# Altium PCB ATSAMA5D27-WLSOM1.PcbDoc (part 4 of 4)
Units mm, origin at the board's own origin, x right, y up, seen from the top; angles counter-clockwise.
Board outline 40.8 x 40.8 mm, 6 copper layers (L1 - Top, L2 - GND, L3 - Signal, L4 - Signal, L5 - PWR, L6 - Bottom), stack 1.144 mm thick; 196 components, 221 nets, 1038 pads, 713 vias.
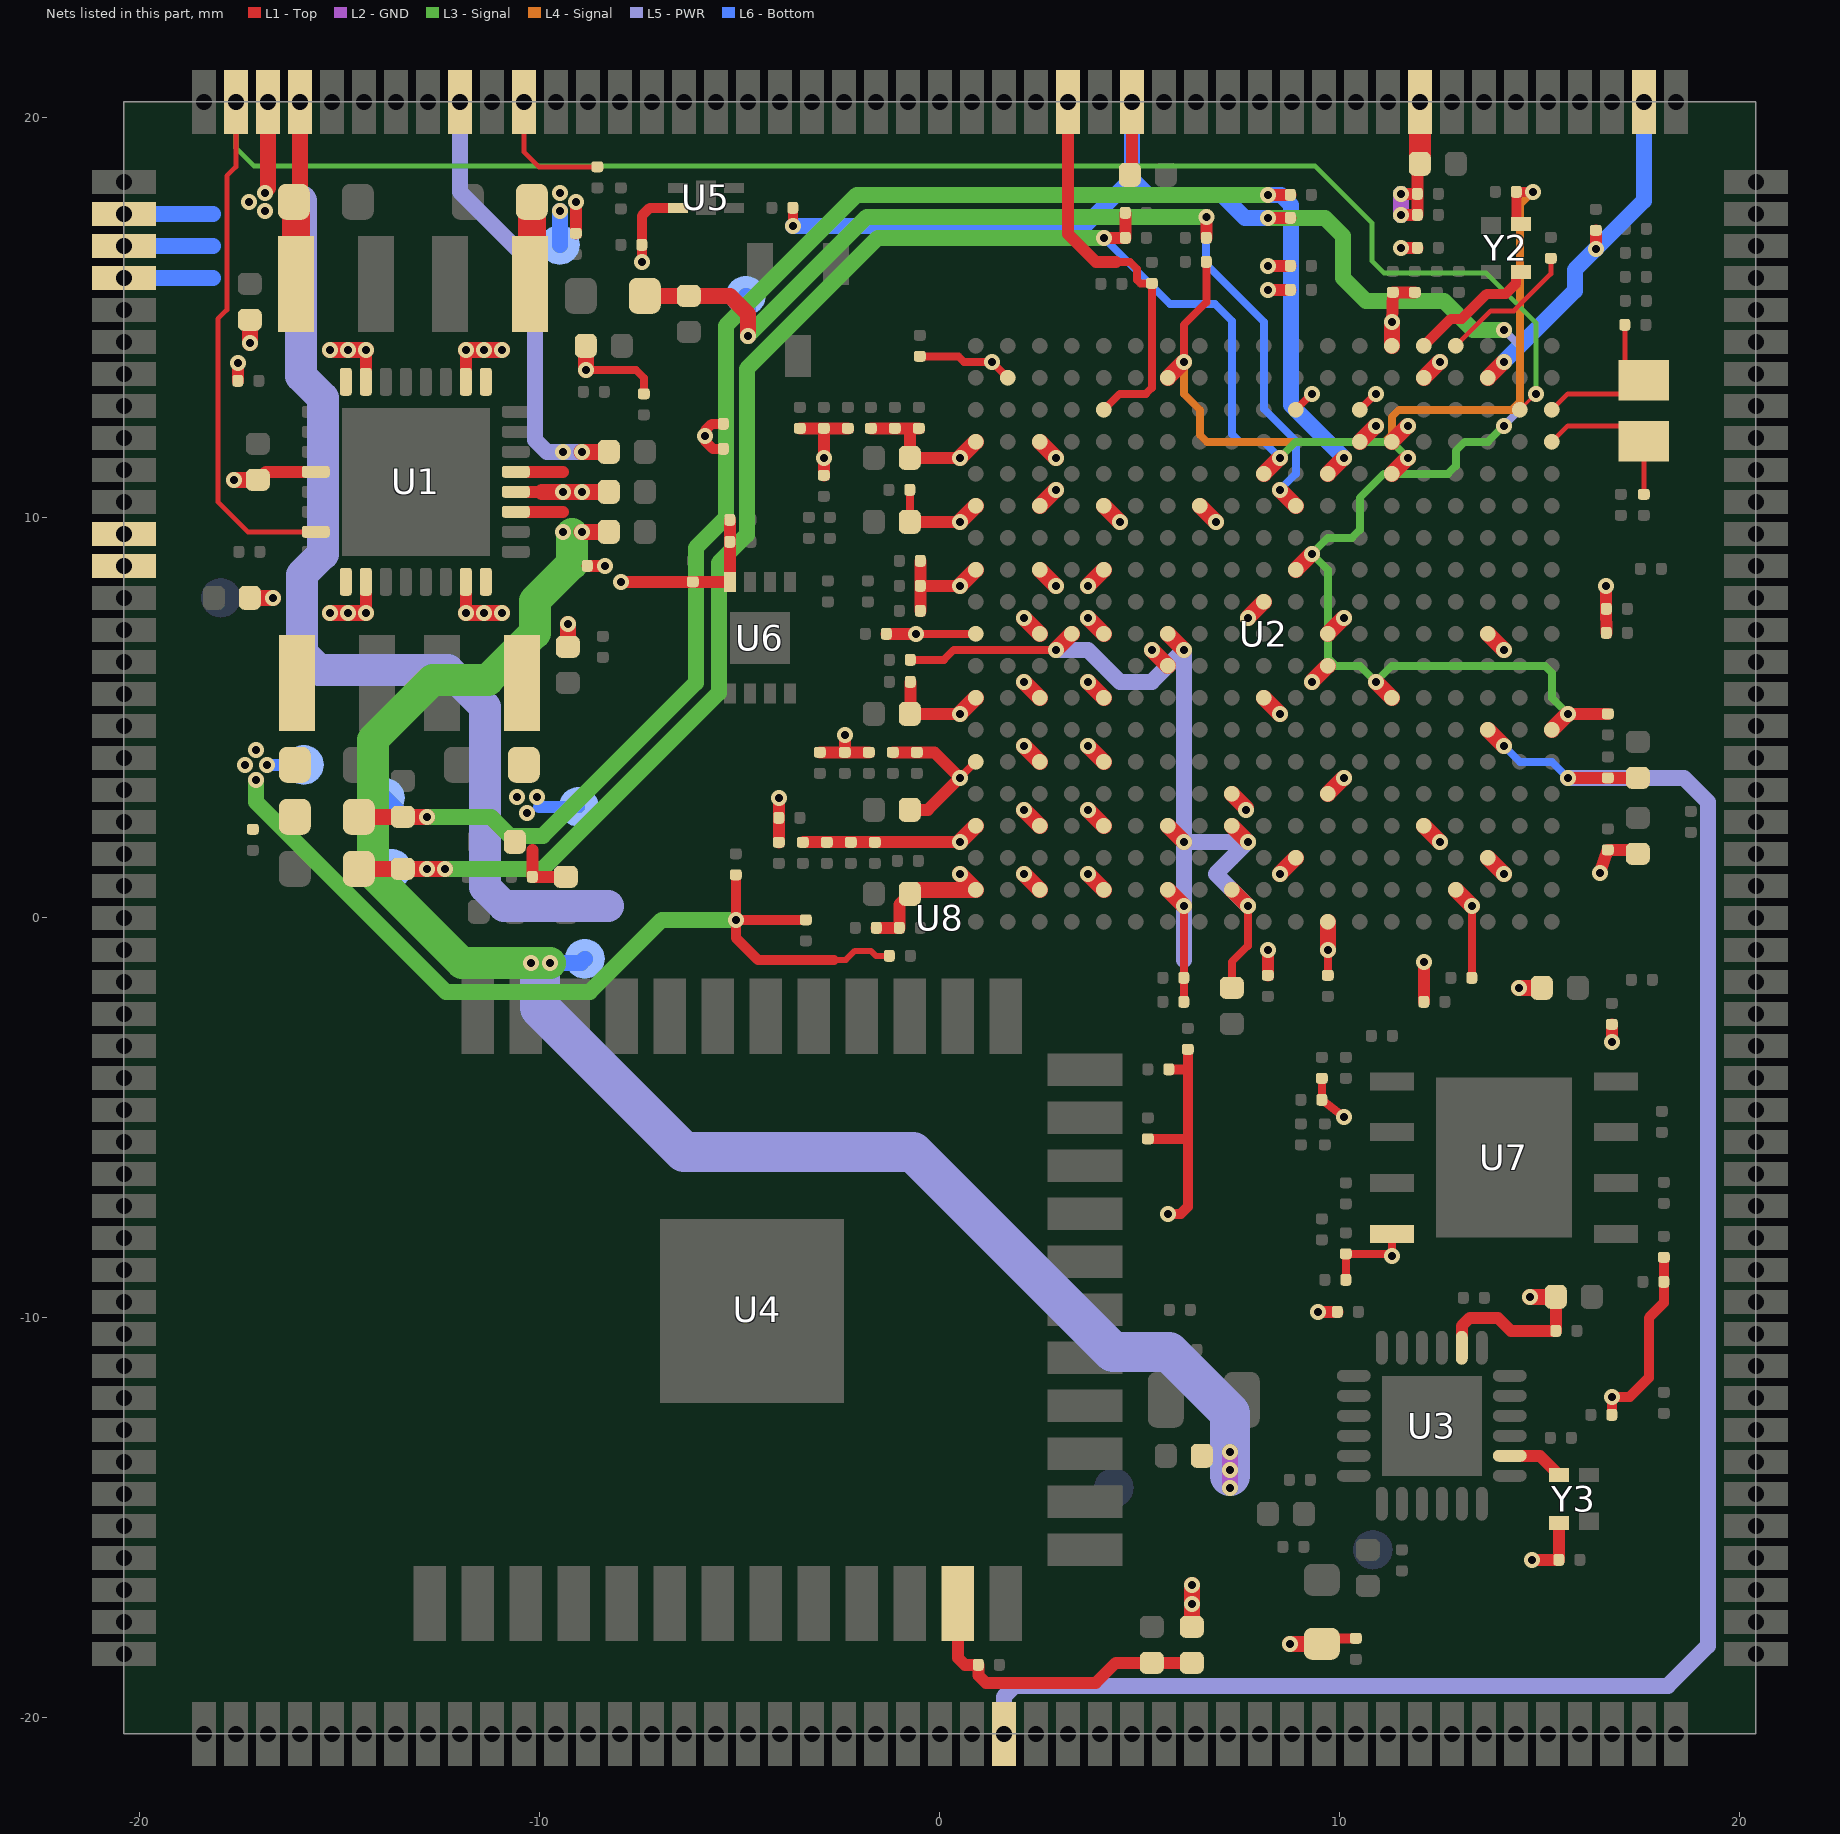
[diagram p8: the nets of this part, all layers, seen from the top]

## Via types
v1: diameter 0.4, hole 0.2, L1 - Top to L6 - Bottom, 680 vias
v2: diameter 0.4, hole 0.2, L1 - Top to L6 - Bottom, tented both sides, 17 vias
v3: diameter 0.4, hole 0.2, L1 - Top to L6 - Bottom, tented bottom, 16 vias

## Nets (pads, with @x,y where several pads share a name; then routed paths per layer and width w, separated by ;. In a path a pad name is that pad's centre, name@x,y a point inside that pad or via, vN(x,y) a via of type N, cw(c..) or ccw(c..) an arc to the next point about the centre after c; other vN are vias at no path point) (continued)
VDD_3V3: C2.1 C38.2 C46.1 C48.1 C51.1 C53.1 C57.1 C88.2 C89.2 C90.2 C95.2 C96.2 FB1.1 FB2.2 FB4.1 L1.2 R4.1 R6.2 R13.2 R14.2 R20.2 R21.2 R24.2 R26.2 R28.2 R29.2 R30.2 R31.2 R32.2 R36.2 R37.2 R38.2 R39.2 R40.2 R41.2 R42.2 R43.2 TP2.1 U1.9 U2.A8 U2.B4 U2.D5 U2.V13 U2.V18 U3.14 U6.8 U7.8 U8.12 U8.13 Y2.4 Y3.4 | length 82.2
  L1 - Top w0.15: -2.65,-1.05 -2.35,-1.05 -2.125,-0.825 -1.725,-0.825 -1.6,-0.95 R28.2@-1.262,-0.95
  L1 - Top w0.2: C51.1@-0.5,14.038 0.463,14.038 0.6,13.9 v1(1.3,13.9) U2.V18@1.7,13.5 ; v1(6.1,13.9) 6.1,14.825 6.662,15.387 C53.1@6.662,16.4 ; R37.2@9.55,-4.012 R41.2@9.55,-4.55 v1(10.1,-4.975) ; C57.1@9.7,-1.4 v1(9.7,-0.8) ; C96.2@10.15,-9 R40.2@10.15,-8.4 11.3,-8.4 U7.8@11.3,-7.9 ; C48.1@13.3,-1.5 v1(13.3,0.3)
  L1 - Top w0.25: R14.2@-5.412,11.725 -5.675,11.725 -5.875,11.925 v1(-5.875,12.05) -5.875,12.175 -5.7,12.35 R13.2@-5.412,12.35 ; R26.2@-5.1,1.075 v1(-5.1,-0.05) ; R29.2@-3.35,-0.05 v1(-5.1,-0.05) ; -2.65,-1.05 -4.55,-1.05 -5.1,-0.5 v1(-5.1,-0.05) ; R32.2@5.2,-5.525 6.2,-5.525 ; v1(5.7,-7.4) 6.025,-7.4 6.2,-7.225 6.2,-5.525 ; R31.2@5.725,-3.788 6.2,-3.788 ; R30.2@6.2,-3.287 6.2,-3.788 ; FB2.2@9.55,-18.15 9.688,-18.013 R24.2@10.4,-18.013 ; Y2.4@14.412,17.35 C38.2@14.412,18.15 v1(14.825,18.15) ; R21.2@16.8,-12.425 v1(16.8,-11.975) 17.25,-11.975 17.725,-11.5 17.725,-10 18.1,-9.625 R36.2@18.1,-9.1 R38.2@18.1,-8.487 ; 6.2,-5.525 6.2,-3.788
  L1 - Top w0.3: R6.2@-17.55,13.425 v1(-17.55,13.875) ; v1(-7.975,8.4) C95.2@-6.175,8.4 -6.173,8.398 U6.8@-5.25,8.398 R43.2@-5.25,9.95 ; v1(9.45,-9.85) R20.2@9.938,-9.85 ; C46.1@12.1,-2.1 v1(12.1,-1.1) ; U3.14@13.05,-10.75 13.05,-10.2 13.25,-10 13.95,-10 14.275,-10.325 C89.2@15.4,-10.325 C88.2@15.4,-9.475 ; v1(14.8,-16.05) C90.2@15.475,-16.05 Y3.4@15.475,-15.125 ; v1(16.8,-3.1) R39.2@16.8,-2.662
  L1 - Top w0.4: U2.V13@5.7,13.5 v1(6.1,13.9) ; FB4.1@6.3,-17.725 v1(6.3,-17.15) v1(6.3,-16.675) ; v1(8.75,-18.15) FB2.2@9.55,-18.15 ; v1(9.7,-0.8) U2.A8@9.7,-0.1 ; U2.D5@12.1,2.3 v1(12.5,1.9) ; U2.B4@12.9,0.7 v1(13.3,0.3) ; v1(14.75,-9.475) C88.2@15.4,-9.475
  L3 - Signal w0.4: v1(-17.1,3.45) -17.1,2.9 -12.35,-1.85 -8.75,-1.85 -6.95,-0.05 v1(-5.1,-0.05)
  L4 - Signal w0.2: v1(6.1,13.9) 6.1,13.1 6.5,12.7 6.5,12.075 6.675,11.9 11.125,11.9 11.3,12.075 11.3,12.525 11.475,12.7 14.3,12.7 14.5,12.9 14.5,17.825 v1(14.825,18.15)
  L6 - Bottom w0.3: v1(-16.825,3.825) TP2.1@-15.9,3.825
  other v1: 11.3,-8.45 -17.375,3.825 -17.1,4.2
VDD_DDR: C9.1 C76.1 C78.1 C80.1 C82.1 L6.2 U1.32 U2.B11 U2.B13 U2.D11 U2.D13 U2.K13 U2.K16 U8.185 U8.186 | length 58.6
  L1 - Top w0.2: C76.1@-0.738,6.45 0.1,6.45 0.35,6.7 v1(2.9,6.7) ; C80.1@6.1,-2.1 C78.1@6.1,-1.5 v1(6.1,0.3) ; C82.1@7.3,-1.75 7.3,-1.1 7.7,-0.7 v1(7.7,0.3)
  L1 - Top w0.4: v2@-16.8,18.25 U8.186@-16.8,20.4 ; C9.1@-16,17.9 U8.185@-16,20.4 ; v1(2.9,6.7) U2.K16@3.3,7.1 ; U2.B13@5.7,0.7 v1(6.1,0.3) ; U2.D13@5.7,2.3 v1(6.1,1.9) ; U2.K13@5.7,7.1 v1(6.1,6.7) ; U2.B11@7.3,0.7 v1(7.7,0.3) ; U2.D11@7.3,2.3 v1(7.7,1.9)
  L1 - Top w0.7: L6.2@-16.1,15.85 C9.1@-16.1,17.9
  L5 - PWR w0.4: v1(2.9,6.7) 3.7,6.7 4.5,5.9 5.3,5.9 v1(6.1,6.7) v1(6.1,1.9) ; 6.1,-1.05 v1(6.1,0.3) v1(6.1,1.9) ; v1(7.7,0.3) 6.9,1.1 v1(7.7,1.9) v1(6.1,1.9)
  L5 - PWR w0.8: -15.975,17.925 -15.975,13.55 -15.425,13 -15.425,9.1 -15.95,8.575 -15.95,6.625 -15.525,6.2 -12.3,6.2 -11.375,5.275 -11.375,0.775 -10.9,0.3 -8.3,0.3
  other v2: -16.875,17.675 -17.275,17.9 -16.875,18.125
VDD_MAIN: C1.2 C4.2 C6.2 C8.2 C10.2 C13.2 C94.2 R1.2 R58.1 U1.4 U1.10 U1.15 U1.20 U1.26 U1.31 U5.4 U8.2 U8.3 U8.4 | length 24.7
  L1 - Top w0.2: v2(-8.85,13.7) -7.6,13.7 -7.4,13.5 R1.2@-7.4,13.1
  L1 - Top w0.25: v1(-7.45,16.4) -7.45,17.55 -7.25,17.75 U5.4@-6.55,17.75
  L1 - Top w0.3: C10.2@-17.05,10.95 -16.85,11.15 U1.4@-15.6,11.15 ; v2(-14.35,7.625) U1.10@-14.35,8.4 ; U1.31@-14.35,13.4 v2(-14.35,14.2) ; v1(-11.85,7.625) U1.15@-11.85,8.4 ; U1.26@-11.85,13.4 v2(-11.85,14.2) ; U1.20@-10.6,10.65 -9.95,10.65 ; R58.1@-8.813,8.8 v1(-8.375,8.8)
  L1 - Top w0.4: v1(-17.65,10.95) C10.2@-17.05,10.95 ; C1.2@-17.25,8 v1(-16.675,8) ; v2(-17.25,14.375) C8.2@-17.25,14.95 ; v2(-15.25,7.625) v2(-14.8,7.625) v2(-14.35,7.625) ; v2(-15.25,14.2) v2(-14.8,14.2) v2(-14.35,14.2) ; v1(-11.85,7.625) v1(-11.4,7.625) v1(-10.95,7.625) ; v2(-11.85,14.2) v2(-11.4,14.2) v2(-10.95,14.2) ; -9.95,10.65 v2(-9.425,10.65) v2(-8.95,10.65) C13.2@-8.275,10.65 ; C4.2@-9.3,6.775 v1(-9.3,7.35) ; v2(-8.85,13.7) C6.2@-8.85,14.3
  L6 - Bottom w0.4: U8.4@-20.4,16 -18.175,16 ; U8.3@-20.4,16.8 -18.175,16.8 ; U8.2@-20.4,17.6 -18.175,17.6
VDDANA: C60.1 C63.1 C101.1 R27.2 U2.G1 U2.H6 U2.M9 U8.159 | length 47.5
  L1 - Top w0.25: v1(-3.675,17.3) R27.2@-3.675,17.75
  L1 - Top w0.3: C101.1@4.75,18.575 4.8,18.625 U8.159@4.8,20.4 ; v1(8.2,17.5) C60.1@8.763,17.5 ; v1(15.7,5.1) C63.1@16.7,5.1
  L1 - Top w0.4: U2.M9@8.9,8.7 v1(9.3,9.1) ; v1(10.9,5.9) U2.H6@11.3,5.5 ; U2.G1@15.3,4.7 v1(15.7,5.1)
  L3 - Signal w0.2: v1(14.1,12.3) 13.7,11.9 13.125,11.9 12.9,11.675 12.9,11.3 12.7,11.1 11.1,11.1 10.5,10.5 10.5,9.7 10.3,9.5 9.7,9.5 v1(9.3,9.1) 9.7,8.7 9.7,6.5 9.9,6.3 10.5,6.3 v1(10.9,5.9) 11.3,6.3 15.125,6.3 15.3,6.125 15.3,5.5 v1(15.7,5.1)
  L3 - Signal w0.4: v1(8.2,17.5) 9.625,17.5 10.075,17.05 10.075,16 10.65,15.425 12.6,15.425 13.325,14.7 v1(14.1,14.7)
  L5 - PWR w0.2: v1(14.1,12.3) 14.5,12.7 14.5,14.3 v1(14.1,14.7)
  L6 - Bottom w0.4: v1(-3.675,17.3) 3.625,17.3 4.8,18.475 ; U8.159@4.8,20.4 4.8,18.475 ; v1(8.2,17.5) 7.625,17.5 7.05,18.075 5.2,18.075 4.8,18.475
VDDBU: C66.1 U2.V3 U8.143 | length 9
  L1 - Top w0.3: v1(16.4,16.725) C66.1@16.4,17.188
  L1 - Top w0.4: U2.V3@13.7,13.5 v1(14.1,13.9)
  L6 - Bottom w0.4: v1(14.1,13.9) 15.875,15.675 15.875,16.2 v1(16.4,16.725) 17.6,17.925 U8.143@17.6,20.4
VDDCORE: C7.1 C20.1 C22.1 C24.1 C26.1 C28.1 C30.1 C32.1 C34.1 C36.1 C43.1 C77.1 L4.2 R8.1 TP7.1 U1.25 U2.C3 U2.C9 U2.K3 U2.K8 U2.T6 U2.U7 U2.U9 U2.V5 U2.W6 | length 15.3
  L1 - Top w0.2: U2.U9@8.9,12.7 v1(9.3,13.1) ; U2.U7@10.5,12.7 v1(10.9,13.1)
  L1 - Top w0.3: R8.1@-9.1,17.112 v1(-9.1,17.9) ; C34.1@8.2,-1.438 v1(8.2,-0.8) ; v1(8.2,15.7) C43.1@8.763,15.7 ; v1@8.2,16.3 C24.1@8.763,16.3 ; v1(11.3,14.9) C32.1@11.325,15.638 C28.1@11.875,15.638 ; v1(11.525,16.75) C77.1@11.938,16.75 ; v1(16.5,1.125) C36.1@16.7,1.7 17.35,1.7 C20.1@17.45,1.6 ; v1(16.65,8.3) 16.656,7.725 C30.1@16.663,7.125
  L1 - Top w0.4: v1(8.5,1.1) U2.C9@8.9,1.5 ; U2.K8@9.7,7.1 v1(10.1,7.5) ; U2.T6@11.3,11.9 v1(11.7,12.3) ; U2.W6@11.3,14.3 v1(11.3,14.9) ; U2.V5@12.1,13.5 v1(12.5,13.9) ; U2.C3@13.7,1.5 v1(14.1,1.1) ; U2.K3@13.7,7.1 v1(14.1,6.7) ; v1(14.475,-1.75) C22.1@14.95,-1.75
  L1 - Top w0.7: L4.2@-10.2,15.9 C7.1@-10.2,17.9
  L6 - Bottom w0.4: TP7.1@-9.5,16.825 v1(-9.5,17.675)
  other v1: 8.2,16.29 -9.5,18.125
VDDFUSE: C40.1 U2.U15 U8.161 | length 10.1
  L1 - Top w0.2: U2.U15@4.1,12.7 4.5,13.1 5.15,13.1 5.3,13.25 C40.1@5.3,15.863 5.012,15.863 4.925,15.95 4.925,16.225 4.75,16.4 4.4,16.4
  L1 - Top w0.3: U8.161@3.2,20.4 3.2,17.1 3.9,16.4 4.4,16.4
VDDIO: C93.2 C105.2 FB4.2 U4.12 | length 7.8
  L1 - Top w0.3: U4.12@0.45,-17.14 0.45,-18.5 0.625,-18.675 C93.2@0.962,-18.675 0.962,-18.937 1.15,-19.125 3.9,-19.125 4.4,-18.625 C105.2@5.3,-18.625 FB4.2@6.3,-18.625
VDDIODDR: C5.1 C11.2 C12.2 C21.1 C23.1 C25.1 C27.1 C29.1 C31.1 C33.1 C35.1 C37.1 C39.1 C41.1 C42.1 C44.1 C45.1 C47.1 C49.1 C50.1 C52.1 C54.1 C55.1 C56.1 C58.1 C59.1 C64.1 C65.1 C67.1 C68.1 C70.1 C71.1 C73.1 C74.1 L3.2 R9.2 TP6.1 U1.16 U2.B15 U2.B17 U2.B19 U2.D15 U2.D17 U2.D19 U2.E8 U2.E11 U2.F15 U2.F17 U2.F19 U2.H10 U2.H15 U2.H17 U2.H19 U2.J8 U2.J13 U2.K15 U2.K17 U2.K19 U2.L10 U2.M15 U2.M17 U2.M19 U2.P12 U2.P15 U2.P17 U2.P19 U2.T17 U2.T19 | length 46.4
  L1 - Top w0.2: C25.1@-0.75,9.9 C68.1@-0.75,10.7 ; v1@-0.55,7.1 v1(-0.6,7.1) U2.K19@0.9,7.1 ; v1(0.5,3.5) U2.F19@0.9,3.9 ; v1(7.65,2.7) v1@7.65,2.75
  L1 - Top w0.3: -10.188,1.7 C11.2@-10.188,1.025 R9.2@-9.35,1.025 ; C45.1@-4.025,1.887 C31.1@-4.025,2.5 v1(-4.025,3) ; C39.1@-3.5,12.238 C37.1@-2.9,12.238 ; C49.1@-3.412,1.9 -2.225,1.9 v1(0.5,1.9) ; C50.1@-3,4.137 C44.1@-2.375,4.137 ; C42.1@-2.9,11.063 v1(-2.9,11.5) C37.1@-2.9,12.238 ; v1(-2.375,4.575) C44.1@-2.375,4.137 ; C54.1@-2.3,12.238 C37.1@-2.9,12.238 ; C74.1@-1.775,4.137 C44.1@-2.375,4.137 ; C55.1@-1.725,12.238 C56.1@-1.125,12.238 -0.75,12.238 ; C73.1@-1.587,-0.25 C41.1@-1.012,-0.25 -1.012,0.338 C65.1@-0.75,0.6 ; C67.1@-1.338,7.1 v1(-0.6,7.1) ; C47.1@-1.175,4.137 C29.1@-0.575,4.137 -0.137,4.137 v1(0.5,3.5) -0.3,2.7 C21.1@-0.7,2.7 ; C25.1@-0.75,9.9 v1(0.5,9.9) ; C71.1@-0.738,5.9 -0.738,5.112 C64.1@-0.75,5.1 0.45,5.1 v1@0.5,5.15 ; C59.1@-0.525,12.238 -0.75,12.238 ; C58.1@-0.488,7.675 C27.1@-0.488,8.3 ; C35.1@-0.488,8.925 C27.1@-0.488,8.3 ; v1@0.45,11.5 C23.1@-0.75,11.5 -0.75,12.238 ; v1(0.5,8.3) C27.1@-0.488,8.3
  L1 - Top w0.4: C65.1@-0.725,0.7 U2.B19@0.9,0.7 v1(0.5,1.1) ; v1(0.5,1.9) U2.D19@0.9,2.3 ; v1(0.5,5.1) U2.H19@0.9,5.5 ; v1(0.5,8.3) U2.M19@0.9,8.7 ; v1(0.5,9.9) U2.P19@0.9,10.3 ; v1(0.5,11.5) U2.T19@0.9,11.9 ; v1(2.1,1.1) U2.B17@2.5,0.7 ; v1(2.1,2.7) U2.D17@2.5,2.3 ; v1(2.1,4.3) U2.F17@2.5,3.9 ; v1(2.1,5.9) U2.H17@2.5,5.5 ; v1(2.1,7.5) U2.K17@2.5,7.1 ; U2.M17@2.5,8.7 v1(2.9,8.3) ; U2.P17@2.5,10.3 v1(2.9,10.7) ; U2.T17@2.5,11.9 v1(2.9,11.5) ; v1(3.7,1.1) U2.B15@4.1,0.7 ; v1(3.7,2.7) U2.D15@4.1,2.3 ; v1(3.7,4.3) U2.F15@4.1,3.9 ; v1(3.7,5.9) U2.H15@4.1,5.5 ; v1(3.7,7.5) U2.K15@4.1,7.1 ; v1(3.7,8.3) U2.M15@4.1,8.7 ; U2.P15@4.1,10.3 v1(4.5,9.9) ; v1(5.3,6.7) U2.J13@5.7,6.3 ; U2.P12@6.5,10.3 v1(6.9,9.9) ; U2.E11@7.3,3.1 v1@7.65,2.75 ; v1(7.7,7.5) U2.L10@8.1,7.9 ; U2.H10@8.1,5.5 v1(8.5,5.1) ; v1(9.3,5.9) U2.J8@9.7,6.3 ; U2.E8@9.7,3.1 v1(10.1,3.5)
  L6 - Bottom w0.3: -10.025,2.775 TP6.1@-9.025,2.775
  other v1: -10.325,2.625 -10.575,3.025 -10.075,3.025
VDDISC: C69.1 C99.2 U2.G3 U8.73 | length 48.1
  L1 - Top w0.3: v1(15.7,3.5) C69.1@16.7,3.5 C99.2@17.45,3.5
  L1 - Top w0.4: U2.G3@13.7,4.7 v1(14.1,4.3)
  L5 - PWR w0.4: U8.73@1.6,-20.4 1.6,-19.475 1.875,-19.2 18.2,-19.2 19.2,-18.2 19.2,2.9 18.6,3.5 v1(15.7,3.5)
  L6 - Bottom w0.2: v1(14.1,4.3) 14.5,3.9 15.3,3.9 v1(15.7,3.5)
VDDOSC_PLL: C3.2 C72.1 C79.1 L2.2 TP3.1 U2.R6 U2.R10 | length 45.4
  L1 - Top w0.3: v1(4.1,17) C79.1@4.638,17 C72.1@4.638,17.625
  L1 - Top w0.4: L2.2@-14.525,1.225 C3.2@-13.425,1.225 v1(-12.825,1.225) v1(-12.375,1.225) ; U2.R10@8.1,11.1 v1(8.5,11.5) ; U2.R6@11.3,11.1 v1(11.7,11.5)
  L3 - Signal w0.2: v1(8.5,11.5) 8.9,11.9 11.3,11.9 v1(11.7,11.5)
  L3 - Signal w0.4: v1(-12.825,1.225) v1(-12.375,1.225) -9.925,1.225 -5.525,5.625 -5.525,8.875 -4.825,9.575 -4.825,13.725 -1.55,17 v1(4.1,17)
  L6 - Bottom w0.2: v1(4.1,17) 5.75,15.35 6.875,15.35 7.3,14.925 7.3,12.1 7.5,11.9 8.1,11.9 v1(8.5,11.5)
  L6 - Bottom w0.4: TP3.1@-13.7,1.225 v1(-12.825,1.225) v1(-12.375,1.225)
VDDPLLA: C81.1 C98.2 L5.2 TP8.1 U2.P9 | length 26
  L1 - Top w0.3: C81.1@6.662,17 v1(6.662,17.525)
  L1 - Top w0.4: L5.2@-7.375,15.55 C98.2@-6.275,15.55 -5.25,15.55 -4.8,15.1 v1(-4.8,14.55) ; v1(8.5,10.7) U2.P9@8.9,10.3
  L3 - Signal w0.4: v1(-4.8,14.55) -1.825,17.525 v1@6.65,17.525
  L6 - Bottom w0.2: v1@6.65,17.525 6.65,16.35 8.1,14.9 8.1,12.725 8.9,11.925 8.9,11.1 v1(8.5,10.7)
  L6 - Bottom w0.4: TP8.1@-4.85,15.55 -4.8,15.5 v1(-4.8,14.55)
VDDSDHC: C83.1 C100.1 C107.1 U2.T7 U8.150 | length 6.8
  L1 - Top w0.3: v1(11.525,17.575) C107.1@11.938,17.575 C83.1@11.938,18.1 ; v1(11.525,18.1) C83.1@11.938,18.1 ; C100.1@11.95,18.85 11.937,18.837 C83.1@11.938,18.1
  L1 - Top w0.4: U2.T7@10.5,11.9 v1(10.9,12.3)
  L1 - Top w0.55: C100.1@12,18.85 U8.150@12,20.4
  L2 - GND w0.4: v1(11.525,17.575) v1(11.525,18.1)
  L3 - Signal w0.4: v1(11.525,17.575) v1(11.525,18.1)
  L4 - Signal w0.4: v1(11.525,17.575) v1(11.525,18.1)
  L5 - PWR w0.4: v1(11.525,17.575) v1(11.525,18.1)
  L6 - Bottom w0.4: v1(11.525,17.575) v1(11.525,18.1)
VDDUTMII: C75.1 C97.2 FB1.2 TP1.1 U2.R8 | length 44.3
  L1 - Top w0.3: v1(8.2,18.075) C75.1@8.763,18.075
  L1 - Top w0.4: FB1.2@-14.525,2.525 C97.2@-13.425,2.525 v1(-12.825,2.525) ; U2.R8@9.7,11.1 v1(10.1,11.5)
  L3 - Signal w0.4: v1(-12.825,2.525) -11.225,2.525 -10.75,2.05 -9.925,2.05 -6.1,5.875 -6.1,9.25 -5.35,10 -5.35,14.8 -2.075,18.075 v1(8.2,18.075)
  L6 - Bottom w0.4: TP1.1@-13.875,3 -13.4,2.525 v1(-12.825,2.525) ; v1(8.2,18.075) 8.525,18.075 8.775,17.825 8.775,12.825 v1(10.1,11.5)
VLDO1: C14.2 FB3.1 TP9.1 U1.19 | length 47.5
  L1 - Top w0.3: U1.19@-10.6,10.15 -9.425,10.15
  L1 - Top w0.4: v1@-8.962,9.65 v1(-8.95,9.65) C14.2@-8.275,9.65
  L2 - GND w0.4: v1(7.25,-14.25) v1(7.25,-13.8) v1(7.25,-13.35)
  L3 - Signal w0.4: v1(7.25,-14.25) v1(7.25,-13.8) v1(7.25,-13.35)
  L3 - Signal w0.8: v1(-9.75,-1.125) v1(-10.225,-1.125) -11.95,-1.125 -14.175,1.1 -14.175,4.45 -12.675,5.95 -11.3,5.95 -10.125,7.125 -10.125,7.925 -9.2,8.85 -9.2,9.6
  L4 - Signal w0.4: v1(7.25,-14.25) v1(7.25,-13.8) v1(7.25,-13.35)
  L5 - PWR w1: -10,-1.275 -10,-2.25 -6.4,-5.85 -0.675,-5.85 4.325,-10.85 5.725,-10.85 7.25,-12.375 v1(7.25,-13.35) v1(7.25,-13.8) v1@7.25,-13.95
  L6 - Bottom w0.4: v1(-10.225,-1.125) v1(-9.75,-1.125) -8.975,-1.125 TP9.1@-8.875,-1.025 ; v1@7.25,-14.225 v1(7.25,-13.8) v1(7.25,-13.35)
  other v1: -9.425,9.65
VLDO2: C15.2 U1.21 U8.180 | length 12.4
  L1 - Top w0.3: U1.21@-10.6,11.15 -9.425,11.15
  L1 - Top w0.4: v1@-8.962,11.65 v1(-8.95,11.65) C15.2@-8.275,11.65
  L5 - PWR w0.4: U8.180@-12,20.4 -12,18.15 -10.125,16.275 -10.125,11.95 -9.825,11.65 v1(-9.425,11.65) v1(-8.95,11.65)
VTH: R57.1 U8.178 | length 3.2
  L1 - Top w0.125: U8.178@-10.4,20.4 -10.4,19.15 -10.025,18.775 R57.1@-8.563,18.775
WKUP: U1.7 U2.U2 U8.187 | length 51.3
  L1 - Top w0.1: U2.U2@14.5,12.7 v1(14.9,13.1)
  L1 - Top w0.125: U8.187@-17.6,20.4 -17.6,18.775 -17.825,18.55 -17.825,15.2 -18.05,14.975 -18.05,10.4 -17.3,9.65 U1.7@-15.6,9.65
  L3 - Signal w0.125: U8.187@-17.6,20.4 -17.6,19.25 -17.15,18.8 9.375,18.8 10.8,17.375 10.8,16.425 11.1,16.125 13.65,16.125 14.9,14.875 v1(14.9,13.1)
XIN_24MHz: U2.W5 Y2.3 | length 3.2
  L1 - Top w0.25: U2.W5@12.1,14.3 12.775,14.975 13.05,14.975 13.675,15.6 14.15,15.6 14.4,15.85 Y2.3@14.4,16.15
XIN_25MHz: U3.8 Y3.3 | length 1.4
  L1 - Top w0.3: U3.8@14.25,-13.45 15,-13.45 Y3.3@15.475,-13.925
XIN_32KHz: C18.2 U2.U1 Y1.1 | length 3.4
  L1 - Top w0.125: U2.U1@15.3,12.7 15.7,13.1 Y1.1@17.3,13.1 ; Y1.1@17.125,13.55 C18.2@17.125,14.825
XOUT_24MHz: R60.1 U2.W4 | length 3.5
  L1 - Top w0.125: U2.W4@12.9,14.3 13.775,15.175 14.35,15.175 15.275,16.1 R60.1@15.275,16.488
XOUT_32KHz: C19.2 U2.T1 Y1.2 | length 3.5
  L1 - Top w0.125: U2.T1@15.3,11.9 15.7,12.3 Y1.2@17.3,12.3 ; C19.2@17.6,10.587 Y1.2@17.6,11.938
pads on no net: U2.A13 U2.A15 U2.A16 U2.A17 U2.A18 U2.B10 U2.B12 U2.B16 U2.C10 U2.C11 U2.C12 U2.C13 U2.C15 U2.C16 U2.C17 U2.D10 U2.D12 U2.D16 U2.E5 U2.E6 U2.E9 U2.E12 U2.E13 U2.E15 U2.E16 U2.E17 U2.E19 U2.F5 U2.F6 U2.F7 U2.F9 U2.F10 U2.F11 U2.F12 U2.F13 U2.F16 U2.G7 U2.G8 U2.G9 U2.G11 U2.G12 U2.G13 U2.G15 U2.G16 U2.G17 U2.G19 U2.H7 U2.H8 U2.H9 U2.H11 U2.H12 U2.H13 U2.H16 U2.J12 U2.J14 U2.J15 U2.J16 U2.J17 U2.J18 U2.J19 U2.K10 U2.K11 U2.K12 U2.K14 U2.L12 U2.L13 U2.L14 U2.L15 U2.L16 U2.M10 U2.M11 U2.M14 U2.N7 U2.N11 U2.N13 U2.N16 U2.R11 U2.R12 U2.R17 U2.T3 U2.T9 U2.T12 U2.U8 U2.U10 U2.U11 U2.V4 U3.7 U4.3 U4.4 U4.5 U4.6 U4.15 U4.29 U4.30 U4.31 U4.34 U4.35 U6.1 U6.2 U6.3 U6.7

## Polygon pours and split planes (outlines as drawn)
GND on L2 - GND "L2 - GND" (solid, remove dead copper, pour order 227): -20.4,20.4 20.4,20.4 20.4,-20.4 -20.4,-20.4
VDDSDHC on L6 - Bottom "L6 - VDDMMC" (solid, remove dead copper, pour order 234): 9.6,18.35 13.9,18.35 13.9,11.7 9.6,11.7
GND on L6 - Bottom "L6 - GND" (solid, remove dead copper, pour order 236): -20.4,20.4 20.4,20.4 20.4,-20.4 -20.4,-20.4
VDD_MAIN on L6 - Bottom "L6 - VDD_MAIN" (solid, pour order 235): -20.4,17.9 -18.7,17.9 -18.7,18.7 -6.6,18.7 -6.6,6.825 -7.1,6.325 -18.7,6.325 -18.7,15.7 -20.4,15.7
VDD_3V3 on L5 - PWR "L5 - 3V3" (solid, remove dead copper, pour order 233): -20.4,20.4 20.4,20.4 20.4,-20.4 -20.4,-20.4
VDD_DDR on L5 - PWR "L5 - VDD_DDR" (solid, pour order 230): 3.5,6.9 3.9,6.9 4.7,6.1 5.2,6.1 6,6.9 6.5,6.9 6.5,2.7 6.975,2.225 7.675,2.225 7.9,2 7.9,1.8 7.375,1.275 7.375,0.9 7.775,0.5 7.8,0.5 7.9,0.4 7.9,0.2 7.8,0.1 7.8,-1.7 6.475,-3.025 -10.5,-3.025 -10.5,0.7 4.3,0.7 4.3,5.8 3.5,6.6
VDDIODDR on L5 - PWR "L5 - VDDIODDR" (solid, remove dead copper, pour order 231): -11.025,3.725 -2.75,12 5.55,12 8.95,8.6 9.4,6.1 9.5,6 9.5,5.8 9.8,5.5 9.8,4.1 10.3,3.6 10.3,3.2 9.475,2.375 7.025,2.375 6.5,2.9 6.5,6.8 6.3,7 5.9,7 5.4,6.5 4.4,6.5 3.9,7 3.5,7 3.4,6.9 3.4,6.5 4.3,5.6 4.3,0.7 -11.025,0.7
VDDCORE on L5 - PWR "L5 - VDDCORE" (solid, remove dead copper, pour order 232): 20.4,20.4 20.4,-2.1 14.101,-2.1 14.101,0.499 12.9,2.2 11.8,2.2 10.837,-0.4 9.1,-0.4 9.1,-1.1 7.9,-1.1 7.9,-1 7.9,2.375 9.075,2.375 9.5,2.8 6.475,5.825 6.475,14.395 5.485,15.325 -11.8,15.325 -11.8,20.4
GND on L3 - Signal "L3 - GND" (solid, remove dead copper, pour order 228): -20.4,20.4 20.4,20.4 20.4,-20.4 -20.4,-20.4
GND on L4 - Signal "L4 - GND" (solid, remove dead copper, pour order 229): -20.4,20.4 20.4,20.4 20.4,-20.4 -20.4,-20.4
GND on L1 - Top "L1 - Top-GND" (solid, remove dead copper, pour order 238): 2.475,-16.375 5.6,-16.375 5.6,-18 4.675,-18 3.85,-18.825 2.475,-18.825
GND on L1 - Top "L1 - GND" (solid, remove dead copper, pour order 226): -20.4,-20.4 2.525,-20.4 2.525,-3.575 -11.15,-3.575 -11.15,-1.5 -20.4,-1.5

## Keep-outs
Keep-Out Layer:
  text ".Layer_Name" at 174.5,-145.75 h1.5

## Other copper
L1 - Top:
  rectangle net GND: 4.775,-17.2 5.775,-16.2
  rectangle net VLDO1: 6.4,-14.45 7.45,-13.15
  region net GND: -18.7,18.7 -18.7,20.15 -20.15,20.15 -20.15,18.7
  rectangle net GND: 18.7,18.7 20.15,20.15
  region net GND: -17.725,0.3 -19.175,0.3 -19.175,-1.15 -17.725,-1.15
  rectangle net GND: 18.7,-20.15 20.15,-18.7
  rectangle net VBAT: 5.2,-12.1 6.05,-10.6
  rectangle net VBAT: 3.55,-11.4 6.05,-10.6
  rectangle net VDDCORE: -10.4,17.475 -8.9,18.35
  rectangle net VDD_DDR: -17.475,17.45 -15.95,18.35
  rectangle net VDDIODDR: -10.9,1.55 -9.85,5.35
  rectangle net VDDIODDR: -10.6,6.65 -10,8.175
  region net VDDIODDR: -10,8.75 -11.425,8.75 -11.425,8.05 -10,8.05
  rectangle net VDD_3V3: -18.425,2.075 -15.925,7.425
  rectangle net VDD_3V3: -16.325,6.75 -15.625,8.225
  rectangle net VDD_3V3: -16.325,8.05 -14.775,8.75
  rectangle net VLDO2: -9.625,11 -8.75,11.85
  rectangle net VLDO1: -9.625,9.45 -8.75,10.3
  pour cut-out: 0.85,-16.05 1.25,-16.05 1.25,-18.85 0.85,-18.85
  pour cut-out: -6.8,-16.05 -6.8,-19.6 -11.125,-19.6 -11.125,-16.05
  region net VDDCORE: -9.8,13.775 -10.525,13.05 -11.45,13.05 -11.45,13.75 -10.825,13.75 -10.6,13.975 -10.6,14.95 -9.8,14.95
  region net VDD_DDR: -16.55,13.75 -15.85,13.05 -14.75,13.05 -14.75,13.75 -15.375,13.75 -15.65,14.025 -15.65,14.8 -16.55,14.8
  text "'.Layer_Name'" at -18.5,24 h0.6
  text ".ProjectRevisionART" at 209.678,-145.572 h1.5
  text ".Layer_Name" at 174.5,-145.75 h1.5
L2 - GND:
  text "'.Layer_Name'" at -18.5,24 h0.6
  text ".ProjectRevisionART" at 209.678,-145.572 h1.5
  text ".Layer_Name" at 174.5,-145.75 h1.5
L3 - Signal:
  rectangle net VDD_3V3: -17.575,3.25 -16.625,4.4
  rectangle net VLDO1: -9.625,9.275 -8.7,10
  pour cut-out: 14.9,4.8 14.9,0.825 14.5,0.825 14.5,4.8
  pour cut-out: 13.75,-8.75 17.775,-8.75 17.775,-10.25 13.75,-10.25
  pour cut-out: 7.8,-1.125 9,-1.125 9,-2.3 7.8,-2.3
  text "'.Layer_Name'" at -18.5,24 h0.6
  text ".ProjectRevisionART" at 209.678,-145.572 h1.5
  text ".Layer_Name" at 174.5,-145.75 h1.5
L4 - Signal:
  pour cut-out: 4.3,12.3 6.3,12.3 6.3,12.7 4.3,12.7
  pour cut-out: 16.75,-8.1 18.675,-8.1 18.675,-7.175 16.75,-7.175
  pour cut-out: 16.025,10.6 16.025,8.688 15.475,8.688 15.475,10.6
  text "'.Layer_Name'" at -18.5,24 h0.6
  text ".ProjectRevisionART" at 209.678,-145.572 h1.5
  text ".Layer_Name" at 174.5,-145.75 h1.5
L5 - PWR:
  rectangle net VLDO1: -10.5,-1.425 -9.5,-0.775
  rectangle net VDD_DDR: -17.475,17.475 -15.575,18.325
  pour cut-out: -19.4,-18.85 -19.4,-19.1 -19.575,-19.1 -19.575,-18.85
  text "'.Layer_Name'" at -18.5,24 h0.6
  text "'.Layer_Name'" at -18.5,24 h0.6
  text ".ProjectRevisionART" at 209.678,-145.572 h1.5
  text ".Layer_Name" at 174.5,-145.75 h1.5
L6 - Bottom:
  region net GND: -20.15,-18.55 -20.15,-20.15 -18.9,-20.15 -18.9,-18.55
  region net GND: -19.55,-18.9 -19.55,-20.15 -18.55,-20.15 -18.55,-18.9
  region net GND: -18.55,20.15 -20.15,20.15 -20.15,18.9 -18.55,18.9
  region net GND: -18.9,19.55 -20.15,19.55 -20.15,18.55 -18.9,18.55
  region net GND: 20.15,18.55 20.15,20.15 18.9,20.15 18.9,18.55
  region net GND: 19.55,18.9 19.55,20.15 18.55,20.15 18.55,18.9
  rectangle net GND: 18.9,-19.55 20.15,-18.55
  rectangle net GND: 18.55,-20.15 20.15,-18.9
  rectangle net GND: -13.35,-11.85 -12.65,-11.15
  rectangle net GND: -12.35,-11.85 -11.65,-11.15
  rectangle net GND: -11.35,-11.85 -10.65,-11.15
  rectangle net GND: -10.35,-11.85 -9.65,-11.15
  rectangle net GND: -13.35,-10.85 -12.65,-10.15
  rectangle net GND: -12.35,-10.85 -11.65,-10.15
  rectangle net GND: -11.35,-10.85 -10.65,-10.15
  rectangle net GND: -10.35,-10.85 -9.65,-10.15
  rectangle net GND: -13.35,-9.85 -12.65,-9.15
  rectangle net GND: -12.35,-9.85 -11.65,-9.15
  rectangle net GND: -11.35,-9.85 -10.65,-9.15
  rectangle net GND: -10.35,-9.85 -9.65,-9.15
  rectangle net GND: -10.35,-8.85 -9.65,-8.15
  rectangle net GND: -11.35,-8.85 -10.65,-8.15
  rectangle net GND: -12.35,-8.85 -11.65,-8.15
  rectangle net GND: -13.35,-8.85 -12.65,-8.15
  rectangle net GND: -11.5,10.15 -10,11.65
  rectangle net GND: 9,4 10.5,5.5
  rectangle net GND: 11,-7 12.5,-5.5
  rectangle net GND: -2,-16 -0.5,-14.5
  rectangle net GND: 2.5,-11 4,-9.5
  rectangle net GND: 2.5,-4.5 4,-3
  rectangle net VDDCORE: -9.7,17.475 -8.9,18.325
  rectangle net VDD_3V3: -17.575,3.25 -16.625,4.4
  rectangle net VDDIODDR: -10.775,2.425 -9.875,3.225
  pour cut-out: 18.025,-15.975 18.75,-15.975 18.75,-15.7 18.025,-15.7
  pour cut-out: -0.45,-18.125 1.625,-18.125 1.625,-18.875 -0.45,-18.875
  pour cut-out: -11.6,-18 -5.775,-18 -5.775,-18.85 -11.6,-18.85
  pour cut-out: 16.325,11.15 16.325,10.025 16.025,10.025 16,10.05 16,11.15
  pour cut-out: 12.3,13.3 14.3,13.3 14.3,11.3 12.3,11.3
  pour cut-out: -18.2,7.175 -18.2,7.8 -18.725,7.8 -18.725,7.175
  text "'.Layer_Name'" at -18.5,24 h0.6
  text ".ProjectRevisionART" at 209.678,-145.572 h1.5
  text ".Layer_Name" at 174.5,-145.75 h1.5
Multi-Layer:
  text "Exported with Altium Designer .Application_BuildNumber on .Print_Date at .Print_Time" at -10,24 h0.6

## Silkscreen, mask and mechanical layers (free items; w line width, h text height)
Top Overlay:
  text "'.Layer_Name'" at -18.5,24 h0.6
  text "Exported with Altium Designer .Application_BuildNumber on .Print_Date at .Print_Time" at -10,24 h0.6
  text "REV" at 6.225,18.075 h1
  text "'.ProjectRevisionART'" at 9.95,18.075 h1
  text "SAMA5D27" at -3.225,18.025 h1
  text "1" at -19.1,17.425 h1
  text "WLSOM1" at -1.7,16.55 h1
  text "M" at -5.675,-1.3 h4.4 r90
  text ".ProjectRevisionART" at 209.678,-145.572 h1.5
  text ".Layer_Name" at 174.5,-145.75 h1.5
Bottom Overlay:
  text "'.Layer_Name'" at -18.5,24 h0.6
  text "Exported with Altium Designer .Application_BuildNumber on .Print_Date at .Print_Time" at -10,24 h0.6
  text ".ProjectRevisionART" at 209.678,-145.572 h1.5
  text ".Layer_Name" at 174.5,-145.75 h1.5
Top Paste:
  text "'.Layer_Name'" at -18.5,24 h0.6
  text "Exported with Altium Designer .Application_BuildNumber on .Print_Date at .Print_Time" at -10,24 h0.6
  text ".ProjectRevisionART" at 209.678,-145.572 h1.5
  text ".Layer_Name" at 174.5,-145.75 h1.5
Bottom Paste:
  text "'.Layer_Name'" at -18.5,24 h0.6
  text "Exported with Altium Designer .Application_BuildNumber on .Print_Date at .Print_Time" at -10,24 h0.6
  text ".ProjectRevisionART" at 209.678,-145.572 h1.5
  text ".Layer_Name" at 174.5,-145.75 h1.5
Top Solder:
  text "'.Layer_Name'" at -18.5,24 h0.6
  text "Exported with Altium Designer .Application_BuildNumber on .Print_Date at .Print_Time" at -10,24 h0.6
  text ".ProjectRevisionART" at 209.678,-145.572 h1.5
  text ".Layer_Name" at 174.5,-145.75 h1.5
Bottom Solder:
  text "'.Layer_Name'" at -18.5,24 h0.6
  text "Exported with Altium Designer .Application_BuildNumber on .Print_Date at .Print_Time" at -10,24 h0.6
  text ".ProjectRevisionART" at 209.678,-145.572 h1.5
  text ".Layer_Name" at 174.5,-145.75 h1.5
NOTES (M1):
  text ".Layer_Name" at 192.5,-145.75 h1.5
BOARD (M2):
  the board outline again, w0.1
  text ".ProjectRevisionART" at 209.678,-145.572 h1.5
  text ".Layer_Name" at 174.5,-145.75 h1.5
REF POINTS (M3):
  text ".Layer_Name" at 174.5,-145.75 h1.5
FAB (M4):
  drawing of 228 lines, arcs and shapes, not listed
  text "THIS PCB TO BE MANUFACTURED TO MEET ALL ACCEPTANCE LEVELS FROM CLASS 2:" at 112.814,68.362 h1.78
  text "IPC-6013" at 189.366,64.259 h1.78
  text "IPC-A-600" at 138.89,64.141 h1.78
  text "IPC-6012" at 166.83,64.141 h1.78
  text "STANDARD:" at 112.814,63.802 h1.78
  text "X" at 134.266,63.659 h2.6
  text "X" at 162.206,63.659 h2.6
  text "TG 180" at 189.316,59.509 h1.78
  text "TG 130-140" at 166.78,59.391 h1.78
  text "MATERIAL:" at 112.805,58.991 h1.78
  text "FR-4 or Equivalent" at 133.125,58.991 h1.78
  text "X" at 185.016,58.909 h2.6
  text "CONTROLLED IMPEDANCE" at 189.316,54.759 h1.78
  text "MULTILAYER" at 138.84,54.641 h1.78
  text "6" at 162.335,54.641 h1.78
  text "LAYERS" at 166.78,54.641 h1.78
  text "X" at 134.216,54.159 h2.6
  text "X" at 185.016,54.159 h2.6
  text "BURIED VIA" at 189.357,49.818 h1.78
  text "TH VIA" at 138.881,49.7 h1.78
  text "BLIND VIA" at 166.821,49.7 h1.78
  text "X" at 134.257,49.218 h2.6
  text "Cu WEIGHT EXTERNAL LAYERS" at 133.116,44.89 h1.78
  text "35um" at 185.186,44.89 h1.78
  text "FINISHED" at 194.711,44.89 h1.78
  text "35um" at 185.186,40.09 h1.78
  text "Cu WEIGHT INTERNAL LAYERS" at 133.116,40.04 h1.78
  text "FINISHED" at 194.711,40.04 h1.78
  text "FINISHED OVERALL THICKNESS" at 133.116,35.19 h1.78
  text "1.20" at 185.625,35.2 h1.78
  text "mm" at 194.711,35.19 h1.78
  text "0.1" at 209.316,35.19 h1.78
  text "mm" at 217.571,35.19 h1.78
  text "40.8" at 185.65,30.2 h1.78
  text "PCB OUTLINE WIDTH" at 133.116,30.19 h1.78
  text "mm" at 194.711,30.19 h1.78
  text "0.1" at 209.316,30.19 h1.78
  text "mm" at 217.571,30.19 h1.78
  text "PCB OUTLINE HEIGHT" at 133.116,25.19 h1.78
  text "mm" at 194.711,25.19 h1.78
  text "0.1" at 209.316,25.19 h1.78
  text "mm" at 217.571,25.19 h1.78
  text "40.8" at 185.65,25.15 h1.78
  text "COPPER THIEVING ALLOWED" at 133.307,20.358 h1.78
  text "YES" at 190.307,20.358 h1.78
  text "NO" at 207.307,20.358 h1.78
  text "X" at 201.898,19.858 h2.6
  text "FINISH:" at 112.807,15.108 h1.78
  text "ENIG" at 138.807,14.808 h1.78
  text "X" at 134.107,14.188 h2.6
  text "IMMERSION SILVER" at 138.831,9.27 h1.78
  text "IMMERSION TIN" at 138.831,3.77 h1.78
  text "SMOBC WITH SELECTIVE GOLD PLATING ON LANDS" at 138.831,0.065 h1.78
  text "INDICATED. 1um GOLD OVER 5-10 um NICKEL" at 138.831,-3.745 h1.78
  text "SOLDERMASK" at 133.116,-10.58 h1.78
  text "IPC-SM-840 Class T" at 154.706,-10.58 h1.78
  text "SOLDERMASK COLOR" at 133.116,-16.93 h1.78
  text "GREEN HIGH GLOSS" at 164.866,-16.93 h1.78
  text "SILKSCREEN COLOR" at 133.116,-23.28 h1.78
  text "WHITE" at 164.866,-23.28 h1.78
  text "ALL HOLES TO BE LOCATED BY THE COORDINATES FROM THE NC DRILL DATA PROVIDED." at 112.796,-29.63 h1.78
  text "PCB REV" at 180.807,-35.892 h1.78
  text ".ProjectRevisionART" at 194.4,-35.925 h1.78
  text "USE ARTWORK SET NO." at 112.796,-35.98 h1.78
  text "'.ProjectPartNumber'" at 144.35,-36 h1.78
  text "ALL UL LOGO, MANUFACTURER'S ID, AND DATE CODES SHALL BE PLACED" at 112.796,-42.33 h1.78
  text "ON THE BOTTOM SIDE UNLESS OTHERWISE INDICATED." at 112.796,-46.14 h1.78
  text "ANY ALTERNATIVES TO THE ABOVE SPECIFICATIONS MUST FIRST BE APPROVED." at 112.307,-51.392 h1.78
  text "Layer" at 115.725,-59.564 h1.5
  text "Name" at 124.231,-59.564 h1.5
  text "Material" at 143.149,-59.564 h1.5
  text "Thickness" at 170.151,-59.564 h1.5
  text "Constant" at 182.878,-59.564 h1.5
  text "Gerber" at 194.997,-59.564 h1.5
  text "THIS BOARD CONTAINS CONTROLLED IMPEDANCE TRACKS, TRACK AND GAP SIZES ARE AS FOLLOWS:" at -126,-60 h1.5
  text "Top Overlay" at 124.231,-62.564 h1.5
  text "GTO" at 194.997,-62.564 h1.5
  text "TYPE;" at -126,-65 h1.5
  text "Impedance;" at -114.5,-65 h1.5
  text "Tolerance;" at -97,-65 h1.5
  text "Layer;" at -80,-65 h1.5
  text "Reference;" at -68,-65 h1.5
  text "Width (um);" at -51,-65 h1.5
  text "Gap (um);" at -31,-65 h1.5
  text "Top Solder" at 124.231,-65.564 h1.5
  text "Solder Resist" at 143.149,-65.564 h1.5
  text "0,025mm" at 170.151,-65.564 h1.5
  text "4" at 182.878,-65.564 h1.5
  text "GTS" at 194.997,-65.564 h1.5
  text "1" at 115.725,-68.564 h1.5
  text "L1 - Top" at 124.231,-68.564 h1.5
  text "Copper" at 143.149,-68.564 h1.5
  text "0,035mm" at 170.151,-68.564 h1.5
  text "GTL" at 194.997,-68.564 h1.5
  text "DIFF;" at -126,-69.5 h1.5
  text "90ohm;" at -114.5,-69.5 h1.5
  text "+/- 10%;" at -97,-69.5 h1.5
  text "L1;" at -80,-69.5 h1.5
  text "L2;" at -68,-69.5 h1.5
  text "125;" at -51,-69.5 h1.5
  text "200;" at -31,-69.5 h1.5
  text "Dielectric 1" at 124.231,-71.564 h1.5
  text "1 x 3313" at 143.149,-71.564 h1.5
  text "0,090mm" at 170.151,-71.564 h1.5
  text "4,2" at 182.878,-71.564 h1.5
  text "DIFF;" at -126,-72 h1.5
  text "100ohm;" at -114.5,-72 h1.5
  text "+/- 10%;" at -97,-72 h1.5
  text "L1;" at -80,-72 h1.5
  text "L2;" at -68,-72 h1.5
  text "100;" at -51,-72 h1.5
  text "200;" at -31,-72 h1.5
  text "2" at 115.725,-74.564 h1.5
  text "L2 - GND" at 124.231,-74.564 h1.5
  text "Copper" at 143.149,-74.564 h1.5
  text "0,035mm" at 170.151,-74.564 h1.5
  text "G1" at 194.997,-74.564 h1.5
  text "SE;" at -126,-75.5 h1.5
  text "50ohm;" at -114.5,-75.5 h1.5
  text "+/- 10%;" at -97,-75.5 h1.5
  text "L1;" at -80,-75.5 h1.5
  text "L2;" at -68,-75.5 h1.5
  text "125;" at -51,-75.5 h1.5
  text "Dielectric 2" at 124.231,-77.564 h1.5
  text "FR-4" at 143.149,-77.564 h1.5
  text "0,127mm" at 170.151,-77.564 h1.5
  text "4,2" at 182.878,-77.564 h1.5
  text "SE;" at -126,-78 h1.5
  text "50ohm;" at -114.5,-78 h1.5
  text "+/- 10%;" at -97,-78 h1.5
  text "L3;" at -80,-78 h1.5
  text "L2;" at -68,-78 h1.5
  text "125;" at -51,-78 h1.5
  text "3" at 115.725,-80.564 h1.5
  text "L3 - Signal" at 124.231,-80.564 h1.5
  text "Copper" at 143.149,-80.564 h1.5
  text "0,035mm" at 170.151,-80.564 h1.5
  text "G2" at 194.997,-80.564 h1.5
  text "SE;" at -126,-81.5 h1.5
  text "50ohm;" at -114.5,-81.5 h1.5
  text "+/- 10%;" at -97,-81.5 h1.5
  text "L4;" at -80,-81.5 h1.5
  text "L5;" at -68,-81.5 h1.5
  text "125;" at -51,-81.5 h1.5
  text "Dielectric 3" at 124.231,-83.564 h1.5
  text "2 x 7628 + 2 x 1080" at 143.149,-83.564 h1.5
  text "0,500mm" at 170.151,-83.564 h1.5
  text "4,2" at 182.878,-83.564 h1.5
  text "SE;" at -126,-84 h1.5
  text "50ohm;" at -114.5,-84 h1.5
  text "+/- 10%;" at -97,-84 h1.5
  text "L6;" at -80,-84 h1.5
  text "L5;" at -68,-84 h1.5
  text "125;" at -51,-84 h1.5
  text "4" at 115.725,-86.564 h1.5
  text "L4 - Signal" at 124.231,-86.564 h1.5
  text "Copper" at 143.149,-86.564 h1.5
  text "0,035mm" at 170.151,-86.564 h1.5
  text "G3" at 194.997,-86.564 h1.5
  text "Dielectric 4" at 124.231,-89.564 h1.5
  text "FR-4" at 143.149,-89.564 h1.5
  text "0,127mm" at 170.151,-89.564 h1.5
  text "4,2" at 182.878,-89.564 h1.5
  text "5" at 115.725,-92.564 h1.5
  text "L5 - PWR" at 124.231,-92.564 h1.5
  text "Copper" at 143.149,-92.564 h1.5
  text "0,035mm" at 170.151,-92.564 h1.5
  text "G4" at 194.997,-92.564 h1.5
  text "Dielectric 5" at 124.231,-95.564 h1.5
  text "1 x 3313" at 143.149,-95.564 h1.5
  text "0,090mm" at 170.151,-95.564 h1.5
  text "4,2" at 182.878,-95.564 h1.5
  text "6" at 115.725,-98.564 h1.5
  text "L6 - Bottom" at 124.231,-98.564 h1.5
  text "Copper" at 143.149,-98.564 h1.5
  text "0,035mm" at 170.151,-98.564 h1.5
  text "GBL" at 194.997,-98.564 h1.5
  text "Bottom Solder" at 124.231,-101.564 h1.5
  text "Solder Resist" at 143.149,-101.564 h1.5
  text "0,025mm" at 170.151,-101.564 h1.5
  text "4" at 182.878,-101.564 h1.5
  text "GBS" at 194.997,-101.564 h1.5
  text "Bottom Overlay" at 124.231,-104.564 h1.5
  text "GBO" at 194.997,-104.564 h1.5
  text "Total board thickness:" at 115.725,-107.564 h1.5
  text "1,194mm" at 170.151,-107.564 h1.5
  text ".ProjectRevisionFAB" at 209.678,-145.572 h1.5
  text ".Layer_Name" at 174.5,-145.75 h1.5
Case (M5):
  text ".Layer_Name" at 174.5,-145.75 h1.5
Cover (M6):
  text ".Layer_Name" at 174.5,-145.75 h1.5
Terminal Block (M7):
  text ".Layer_Name" at 174.5,-145.75 h1.5
Route Tool Path:
  text ".Layer_Name" at 174.5,-145.75 h1.5
V-Cut (M9):
  text ".Layer_Name" at 174.5,-145.75 h1.5
Assy BOT (M10):
  text ".variantName" at -75.93,-129.75 h0.9
  text "ASSEMBLY VARIANT:" at -61.68,-129.75 h0.9
  text "DOCUMENT NUMBER:" at -107.95,-138 h1.14
  text ".ProjectBoardNumber" at -113.7,-141 h1.78
  text ".ProjectRevisionASSY" at -124.878,-145.572 h1.5
  text ".Layer_Name" at -90,-145.75 h1.5
Assy TOP (M11):
  text "ASSEMBLY NOTES:" at 15.475,-122.1 h4
  text "1. ALL COMPONENTS SHALL BE RoHS COMPLIANT." at -18.625,-127.2 h3
  text "2. ALL UNUSED THROUGH HOLE COMPONENT LOCATIONS SHALL BE FREE OF SOLDER." at -18.625,-130.2 h3
  text "3. ALL COMPONENTS SHALL BE MOUNTED FLUSH TO THE BOARD, EXCEPT AS NOTED." at -18.625,-133.2 h3
  text "4. FINISHED BOARD SHALL BE FREE OF ALL RESIDUES." at -18.625,-136.2 h3
  text "DOCUMENT NUMBER:" at 192.75,-138 h1.14
  text "5. ALL LEADS SHALL BE TRIMMED TO A MAXIMUM HEIGHT OF 2mm" at -18.625,-139.2 h3
  text ".ProjectBoardNumber" at 198.5,-141 h1.78
  text "6. PLACE LABEL  ON THE LOCATION INDICATED." at -18.625,-142.2 h3
  text "7." at -18.625,-145.3 h3
  text ".ProjectRevisionASSY" at 209.678,-145.572 h1.5
  text ".Layer_Name" at 174.5,-145.75 h1.5
3D BOT (M12):
  text ".Layer_Name" at 174.5,-145.75 h1.5
3D TOP (M13):
  text ".Layer_Name" at 174.5,-145.75 h1.5
Guard BOT (M14):
  text ".ProjectRevisionART" at 209.678,-145.572 h1.5
  text ".Layer_Name" at 174.5,-145.75 h1.5
Guard TOP (M15):
  text ".ProjectRevisionART" at 209.678,-145.572 h1.5
  text ".Layer_Name" at 174.5,-145.75 h1.5
TITLE (M16):
  lines w0.1: 146,-128.5 227.82,-128.5 ; 200.275,-121 200.275,-124 227.82,-124 ; 216.54,-145.635 216.54,-144.365 ; 216.54,-145 226.7,-145 ; 216.7,-143.8 216.7,-142.8 ; 216.7,-143.3 226.7,-143.3 ; 219.08,-145.635 219.08,-144.365 ; 221.62,-145.635 221.62,-144.365 ; 221.7,-143.6 221.7,-143 ; 224.16,-145.635 224.16,-144.365 ; 226.7,-145.635 226.7,-144.365 ; 226.7,-143.8 226.7,-142.8 ; 227.82,-124 227.82,-124
  lines w0.127: -148.1,-91.175 -143.02,-91.175 ; -148.1,-30.85 -143.02,-30.85 ; -148.1,29.475 -143.02,29.475 ; -84.6,-151.5 -84.6,-146.42 ; -84.6,84.72 -84.6,89.8 ; -21.1,-151.5 -21.1,-146.42 ; -21.1,84.72 -21.1,89.8 ; 42.4,-151.5 42.4,-146.42 ; 42.4,84.72 42.4,89.8 ; 77.96,-146.42 113.52,-146.42 ; 105.9,-151.5 105.9,-146.42 ; 105.9,84.72 105.9,89.8 ; 112,-146.42 112,-121 227.82,-121 ; 146,-146.42 146,-121 ; 146,-142 227.82,-142 ; 146,-136 227.82,-136 ; 146,-130 227.82,-130 ; 169.4,-151.5 169.4,-146.42 ; 169.4,84.72 169.4,89.8 ; 174,-146.42 174,-130 ; 192,-142 192,-136 ; 205,-146.42 205,-142 ; 212.5,-146.42 212.5,-136 ; 227.82,-115.94 227.82,-146.42 ; 227.82,-91.175 232.9,-91.175 ; 227.82,-30.85 232.9,-30.85 ; 227.82,29.475 232.9,29.475 ; 227.82,-146.42 227.82,84.72 -143.02,84.72 -143.02,-146.42 227.82,-146.42 ; -148.1,-151.5 -148.1,89.8 232.9,89.8 232.9,-151.5 -148.1,-151.5
  lines w0.254: 106,84.5 106,80 ; 117,75.5 117,80 117,84.5 ; 129.5,75.5 129.5,80 129.5,84.5 ; 208,75.5 208,80 208,84.5 ; 227.5,75.5 106,75.5 106,80 ; 227.5,80 106,80
  text "1" at -116.824,86.498 h1.78
  text "2" at -53.434,86.498 h1.78
  text "3" at 9.795,86.498 h1.78
  text "4" at 73.464,86.498 h1.78
  text "5" at 136.939,86.498 h1.78
  text "6" at 200.566,86.498 h1.78
  text "REV" at 108.5,81.5 h1.52
  text "ECO" at 118.5,81.5 h1.52
  text "Comments" at 165,81 h1.52
  text "Date" at 213,81 h1.52
  text "A" at -146.195,57.466 h1.78
  text "A" at 229.725,57.466 h1.78
  text "B" at -146.195,-2.986 h1.78
  text "B" at 229.725,-2.986 h1.78
  text "C" at -146.195,-63.311 h1.78
  text "C" at 229.725,-63.311 h1.78
  text "PART NUMBER:" at 201,-123 h1
  text ".ProjectpartNumber" at 211.5,-123 h1
  text "D" at -146.195,-123.509 h1.78
  text "TITLE:" at 147,-123.5 h1.14
  text "D" at 229.725,-123.509 h1.78
  text ".ProjectTitle" at 147,-127.5 h2.5
  text "ASSEMBLY VARIANT:" at 146.5,-129.75 h1
  text ".VariantName" at 160.75,-129.75 h1
  text "PCB DESIGNER:" at 147,-132 h1.14
  text "GERBER FILE:" at 175,-132 h1.14
  text ".ProjectDrawnBy" at 147,-135 h1.78
  text ".Plot_File_Name" at 175,-135 h1.3
  text "M" at 115,-137 h15.24
  text "ENGINEER:" at 147,-138 h1.14
  text "BOARD NUMBER:" at 175,-138 h1.14
  text "DATE:" at 213.7,-138 h1.14
  text "Microchip Technology Inc." at 113.77,-140.26 h1.78
  text ".ProjectEngineer" at 147,-141 h1.78
  text ".ProjectBoardNumber" at 175.125,-141 h1.78
  text ".PRINT_DATE" at 213.7,-141 h1.5
  text "2355 W. Chandler Blvd." at 115,-143 h1.78
  text "LAYER NAME:" at 175,-143.5 h1.14
  text "10mm" at 213,-143.6 h0.7
  text "PCB FILE NAME:" at 147,-143.75 h1.14
  text "REV:" at 205.75,-143.75 h1.14
  text "400mil" at 212.9,-145.3 h0.7
  text "Chandler, AZ  85224" at 116,-145.5 h1.78
  text ".PCB_FILE_NAME_NO_PATH" at 147,-145.75 h1.14
  text "1" at -116.824,-149.722 h1.78
  text "2" at -53.434,-149.722 h1.78
  text "3" at 9.795,-149.722 h1.78
  text "4" at 73.464,-149.722 h1.78
  text "5" at 136.939,-149.722 h1.78
  text "6" at 200.566,-149.722 h1.78
Drill Drawing:
  lines w0.15: -10.925,-114.175 85.654,-114.175 ; -10.925,-106.675 85.654,-106.675 ; 1.32,-117.925 1.32,-102.925 ; 15.576,-117.925 15.576,-102.925 ; 40.45,-117.925 40.45,-102.925 ; 60.516,-117.925 60.516,-102.925 ; 70.119,-117.925 70.119,-102.925 ; -10.925,-117.925 85.654,-117.925 85.654,-102.925 -10.925,-102.925 -10.925,-117.925 ; -9.461,-112.217 -8.628,-113.05 -7.795,-112.217 -8.628,-111.383 -9.461,-112.217
  text "Symbol" at -8.675,-105.55 h1.8
  text "Hit Count" at 2.445,-105.55 h1.8
  text "Finished Hole Size" at 16.701,-105.55 h1.8
  text "Hole Tolerance" at 41.575,-105.55 h1.8
  text "Plated" at 61.641,-105.55 h1.8
  text "Hole Type" at 71.244,-105.55 h1.8
  text "188" at 2.445,-109.3 h1.5
  text "0,40mm" at 16.701,-109.3 h1.5
  text "PTH" at 61.641,-109.3 h1.5
  text "Round" at 71.244,-109.3 h1.5
  text "X" at -9.334,-109.45 h1.67
  text "713" at 2.445,-113.05 h1.5
  text "0,20mm" at 16.701,-113.05 h1.5
  text "PTH" at 61.641,-113.05 h1.5
  text "Round" at 71.244,-113.05 h1.5
  text "901 Total" at 2.445,-116.8 h1.5
  text "DOCUMENT NUMBER:" at 192.75,-138 h1.14
  text ".ProjectBoardNumber" at 198.5,-141 h1.78
  text ".ProjectRevisionFAB" at 209.678,-145.572 h1.5
TITLE MIRROR (M17):
  lines w0.1: -143,-128.5 -61.18,-128.5 ; -141.9,-145.635 -141.9,-144.365 ; -141.9,-145 -131.74,-145 ; -141.9,-143.8 -141.9,-142.8 ; -141.9,-143.3 -131.9,-143.3 ; -139.36,-145.635 -139.36,-144.365 ; -136.9,-143.6 -136.9,-143 ; -136.82,-145.635 -136.82,-144.365 ; -134.28,-145.635 -134.28,-144.365 ; -131.9,-143.8 -131.9,-142.8 ; -131.74,-145.635 -131.74,-144.365 ; -114,-121 -114,-124 -143,-124 ; -143,-124 -143,-124
  lines w0.127: -148.1,-91.175 -143.02,-91.175 ; -148.1,-30.85 -143.02,-30.85 ; -148.1,29.475 -143.02,29.475 ; -143.02,-142 -61.2,-142 ; -143.02,-136 -61.2,-136 ; -143,-130 -61.18,-130 ; -143,-121 -27.18,-121 -27.18,-146.42 ; -127.7,-146.42 -127.7,-136 ; -120.2,-146.42 -120.2,-142 ; -107.2,-142 -107.2,-136 ; -89.18,-146.42 -89.18,-130 ; -84.6,-151.5 -84.6,-146.42 ; -84.6,84.72 -84.6,89.8 ; -61.18,-146.42 -61.18,-121 ; -21.1,-151.5 -21.1,-146.42 ; -21.1,84.72 -21.1,89.8 ; 42.4,-151.5 42.4,-146.42 ; 42.4,84.72 42.4,89.8 ; 105.9,-151.5 105.9,-146.42 ; 105.9,84.72 105.9,89.8 ; 169.4,-151.5 169.4,-146.42 ; 169.4,84.72 169.4,89.8 ; 227.82,-91.175 232.9,-91.175 ; 227.82,-30.85 232.9,-30.85 ; 227.82,29.475 232.9,29.475 ; -148.1,-151.5 232.9,-151.5 232.9,89.8 -148.1,89.8 -148.1,-151.5 ; -143.02,-146.42 227.82,-146.42 227.82,84.72 -143.02,84.72 -143.02,-146.42
  text "6" at -115.766,86.498 h1.78
  text "5" at -52.139,86.498 h1.78
  text "4" at 11.336,86.498 h1.78
  text "3" at 75.005,86.498 h1.78
  text "2" at 138.234,86.498 h1.78
  text "1" at 201.624,86.498 h1.78
  text "A" at -144.925,57.466 h1.78
  text "A" at 230.995,57.466 h1.78
  text "B" at -144.925,-2.986 h1.78
  text "B" at 230.995,-2.986 h1.78
  text "C" at -144.925,-63.311 h1.78
  text "C" at 230.995,-63.311 h1.78
  text ".ProjectpartNumber" at -127,-123 h1
  text "PART NUMBER:" at -115.5,-123 h1
  text "TITLE:" at -62.18,-123 h1.14
  text "D" at -144.925,-123.509 h1.78
  text "D" at 230.995,-123.509 h1.78
  text ".ProjectTitle" at -62.18,-127.5 h2.5
  text "GERBER FILE:" at -90.18,-132 h1.14
  text "PCB DESIGNER:" at -62.18,-132 h1.14
  text ".Plot_File_Name" at -90.18,-135 h1.5
  text ".ProjectDrawnBy" at -62.18,-135 h1.78
  text "M" at -30.18,-137 h15.24
  text "DATE:" at -128.9,-138 h1.14
  text "BOARD NUMBER:" at -90.2,-138 h1.14
  text "ENGINEER:" at -62.2,-138 h1.14
  text "Microchip Technology Inc." at -28.95,-140.26 h1.78
  text ".PRINT_DATE" at -128.9,-141 h1.5
  text ".ProjectBoardNumber" at -95.2,-141 h1.78
  text "04-" at -90.2,-141 h1.78
  text ".ProjectEngineer" at -62.2,-141 h1.78
  text "2355 W. Chandler Blvd." at -30.18,-143 h1.78
  text "LAYER NAME:" at -90.2,-143.5 h1.14
  text "10mm" at -128.2,-143.6 h0.7
  text "REV:" at -120.95,-143.75 h1.14
  text "PCB FILE NAME:" at -62.2,-143.75 h1.14
  text "400mil" at -128.1,-145.3 h0.7
  text "Chandler, AZ  85224" at -31.18,-145.5 h1.78
  text ".PCB_FILE_NAME_NO_PATH" at -62.2,-145.75 h1.14
  text "6" at -115.766,-149.722 h1.78
  text "5" at -52.139,-149.722 h1.78
  text "4" at 11.336,-149.722 h1.78
  text "3" at 75.005,-149.722 h1.78
  text "2" at 138.234,-149.722 h1.78
  text "1" at 201.624,-149.722 h1.78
